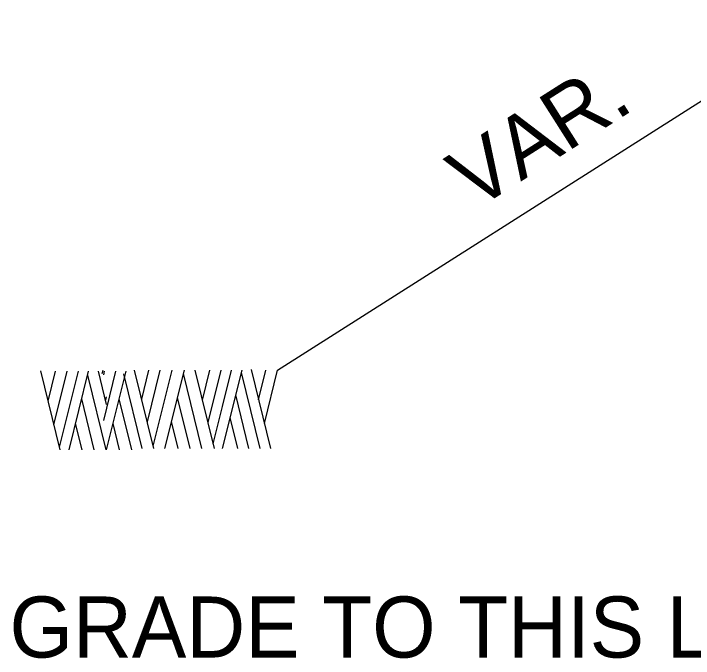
# Model space of a CAD drawing. Extents: x 573748 to 574632, y -54663 to -53209.
# Drawn here: x 574077 to 574096.78, y -54655.58 to -54636.83 of the extents above; entities that cross this region are included whole.
import ezdxf

# ---------------------------------------------------------------- set-up
doc = ezdxf.new("R2010")
doc.units = 0
for name, color, linetype in [('Prop Dimension Text', 7, 'Continuous'), ('Typical Hinge Slope Arterial CELL', 7, 'Continuous'), ('Typical Slope Point Local CELL', 7, 'Continuous')]:
    doc.layers.add(name, color=color, linetype=linetype)

msp = doc.modelspace()

# ---------------------------------------------------------------- linework, layer by layer
at = {"layer": 'Typical Hinge Slope Arterial CELL'}
msp.add_line((574084.683, -54647.194), (574100.995, -54636.83), dxfattribs=at)
at = {"layer": 'Typical Slope Point Local CELL'}
for p, q in [((574078.356, -54649.511), (574077.793, -54647.216)), ((574078.006, -54648.094), (574078.218, -54647.223)), ((574078.175, -54648.781), (574078.561, -54647.223)), ((574078.34, -54649.438), (574078.887, -54647.223)), ((574078.616, -54649.511), (574079.187, -54647.223)), ((574079.71, -54648.19), (574079.47, -54647.223)), ((574079.58, -54647.297), (574079.608, -54647.194)), ((574079.624, -54648.655), (574079.978, -54647.223)), ((574079.624, -54647.334), (574079.647, -54647.223)), ((574079.706, -54649.511), (574080.277, -54647.223)), ((574081.084, -54649.475), (574080.521, -54647.194)), ((574080.734, -54648.035), (574080.939, -54647.194)), ((574080.895, -54648.699), (574081.265, -54647.194)), ((574081.068, -54649.408), (574081.616, -54647.194)), ((574081.403, -54649.475), (574081.97, -54647.194)), ((574082.482, -54649.475), (574081.943, -54647.297)), ((574082.848, -54649.475), (574082.285, -54647.194)), ((574082.498, -54648.065), (574082.71, -54647.194)), ((574082.663, -54648.722), (574083.045, -54647.194)), ((574083.08, -54648.257), (574083.34, -54647.194)), ((574083.08, -54649.475), (574083.647, -54647.194)), ((574084.179, -54649.475), (574083.631, -54647.26)), ((574084.482, -54649.475), (574083.919, -54647.179)), ((574084.128, -54648.057), (574084.34, -54647.194)), ((574084.301, -54648.744), (574084.683, -54647.194)), ((574079.698, -54649.511), (574079.159, -54647.341)), ((574080.746, -54649.475), (574080.21, -54647.304)), ((574079.348, -54649.511), (574078.986, -54648.028)), ((574079.687, -54648.065), (574079.71, -54647.976)), ((574080.439, -54649.511), (574080.076, -54648.028)), ((574082.135, -54649.475), (574081.769, -54647.991)), ((574083.844, -54649.475), (574083.466, -54647.917)), ((574082.813, -54649.334), (574083.08, -54648.257)), ((574081.789, -54649.475), (574081.6, -54648.685)), ((574083.525, -54649.475), (574083.305, -54648.574)), ((574078.994, -54649.511), (574078.809, -54648.744)), ((574080.084, -54649.511), (574079.899, -54648.744))]:
    msp.add_line(p, q, dxfattribs=at)

# ---------------------------------------------------------------- texts
at = {"layer": 'Prop Dimension Text'}
msp.add_text('GRADE TO THIS LINE', height=1.7745, dxfattribs=at).set_placement((574076.885, -54655.551))
at = {"layer": 'Typical Hinge Slope Arterial CELL'}
msp.add_text('VAR.', height=1.7745, rotation=32.4291, dxfattribs=at).set_placement((574090.418, -54642.565))

doc.saveas('drawing.dxf')
